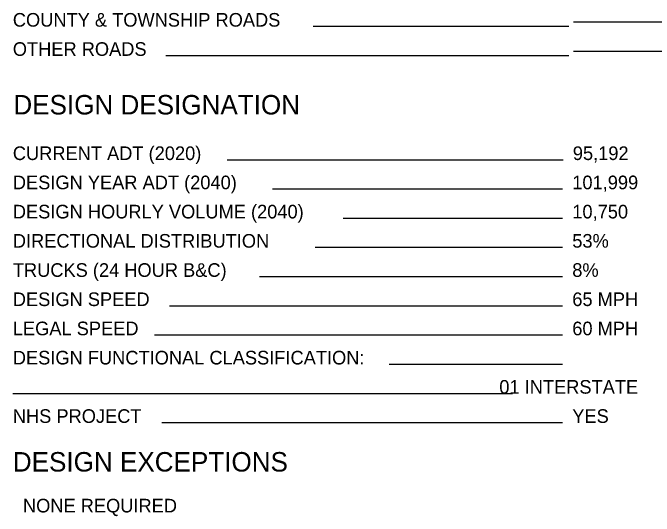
# Model space of a CAD drawing. Extents: x 2080852 to 2433556, y 1080825 to 1306626.
# Drawn here: x 2095577 to 2165094, y 1140685 to 1195291 of the extents above; entities that cross this region are included whole.
import ezdxf

# ---------------------------------------------------------------- set-up
doc = ezdxf.new("R2010")
doc.units = 0
doc.layers.add('PM_P_Lane_Line', color=7, linetype='Continuous')

msp = doc.modelspace()

# ---------------------------------------------------------------- linework, layer by layer
at = {"layer": 'PM_P_Lane_Line'}
for p, q in [((2155828, 1193790), (2128141, 1193790)), ((2169556, 1194273), (2156356, 1194273)), ((2169556, 1191105), (2156356, 1191105)), ((2155828, 1190622), (2112170, 1190622)), ((2155220, 1179319), (2118800, 1179319)), ((2155161, 1176151), (2123718, 1176151)), ((2155161, 1172983), (2131384, 1172983)), ((2155161, 1169815), (2128359, 1169815)), ((2155161, 1166647), (2122309, 1166647)), ((2155161, 1163479), (2112569, 1163479)), ((2155161, 1160311), (2110936, 1160311)), ((2155161, 1157143), (2136368, 1157143)), ((2149732, 1153975), (2095577, 1153975)), ((2155161, 1150807), (2111732, 1150807))]:
    msp.add_line(p, q, dxfattribs=at)

# ---------------------------------------------------------------- texts
for s, height, p in [('COUNTY & TOWNSHIP ROADS', 1478.4, (2095577, 1193790)), ('OTHER ROADS', 1478.4, (2095577, 1190622)), ('DESIGN DESIGNATION', 2112, (2095636, 1184265)), ('CURRENT ADT (2020)', 1478.4, (2095577, 1179319)), ('95,192', 1478.4, (2156276, 1179319)), ('DESIGN YEAR ADT (2040)', 1478.4, (2095577, 1176151)), ('101,999', 1478.4, (2156217, 1176151)), ('DESIGN HOURLY VOLUME (2040)', 1478.4, (2095577, 1172983)), ('10,750', 1478.4, (2156217, 1172983)), ('DIRECTIONAL DISTRIBUTION', 1478.4, (2095577, 1169815)), ('53%', 1478.4, (2156217, 1169815)), ('TRUCKS (24 HOUR B&C)', 1478.4, (2095577, 1166647)), ('8%', 1478.4, (2156217, 1166647)), ('DESIGN SPEED', 1478.4, (2095577, 1163479)), ('65 MPH', 1478.4, (2156217, 1163479)), ('LEGAL SPEED', 1478.4, (2095577, 1160311)), ('60 MPH', 1478.4, (2156217, 1160311)), ('DESIGN FUNCTIONAL CLASSIFICATION:', 1478.4, (2095577, 1157143)), ('                                                                                                01 INTERSTATE', 1478.4, (2095577, 1153975)), ('NHS PROJECT', 1478.4, (2095577, 1150807)), ('YES', 1478.4, (2156217, 1150807)), ('DESIGN EXCEPTIONS', 2112, (2095577, 1145527)), ('  NONE REQUIRED', 1478.4, (2095577, 1141091))]:
    msp.add_text(s, height=height, dxfattribs=at).set_placement(p)

doc.saveas('drawing.dxf')
